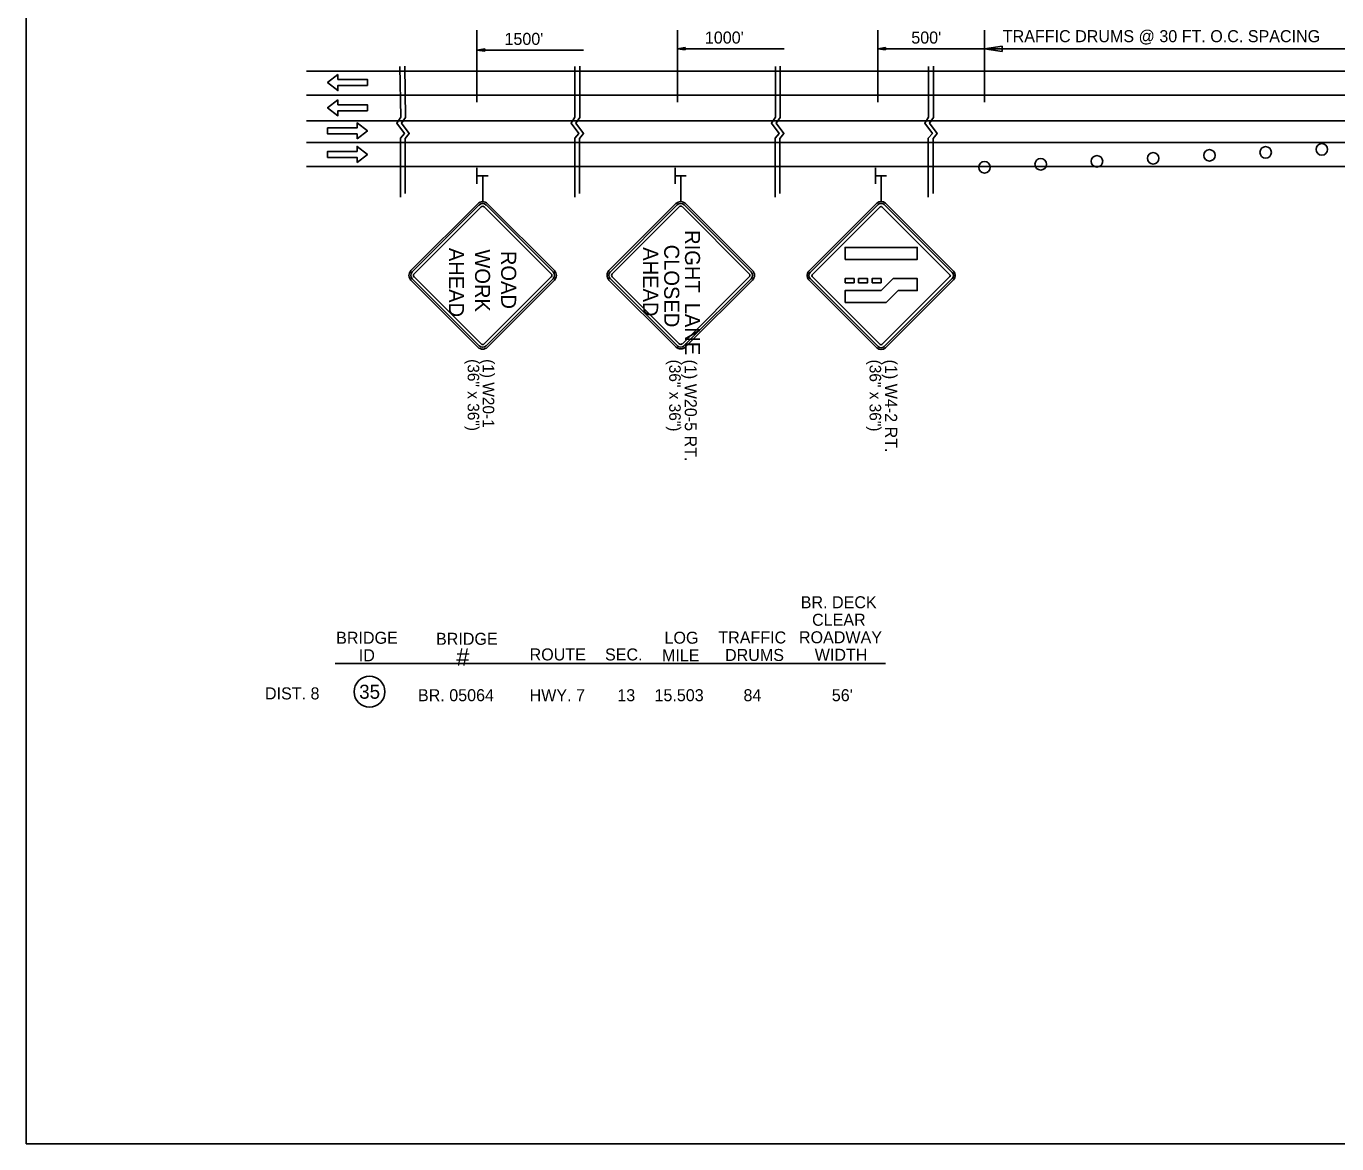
# Model space of a CAD drawing. Extents: x 1930579 to 1938013, y 596452 to 597673.
# Drawn here: x 1936313 to 1936967, y 596573 to 597131 of the extents above; entities that cross this region are included whole.
import ezdxf

# ---------------------------------------------------------------- set-up
doc = ezdxf.new("R2010")
doc.units = 0
for name, color, linetype in [('Default', 7, 'Continuous'), ('P_TC_Signs_Permanent', 7, 'Continuous'), ('P_TC_Signs_Temporary', 7, 'Continuous'), ('R_Annotation', 7, 'Continuous'), ('R_Border', 7, 'Continuous'), ('R_Striping', 7, 'Continuous')]:
    doc.layers.add(name, color=color, linetype=linetype)

msp = doc.modelspace()

# ---------------------------------------------------------------- linework, layer by layer
at = {"layer": 'Default'}
for p, q in [((1936537.79, 597129.19), (1936537.79, 597093.28)), ((1936637.79, 597129.19), (1936637.79, 597093.28)), ((1936737.79, 597129.19), (1936737.79, 597093.28)), ((1936791.02, 597129.19), (1936791.02, 597093.28)), ((1936641.62, 597120.46), (1936637.79, 597119.89)), ((1936641.62, 597119.31), (1936641.62, 597120.46)), ((1936741.62, 597120.46), (1936737.79, 597119.89)), ((1936741.62, 597119.31), (1936741.62, 597120.46)), ((1936791.02, 597119.89), (1936799.89, 597121.22)), ((1936799.89, 597121.22), (1936799.89, 597118.56)), ((1936541.62, 597119.78), (1936537.79, 597119.21)), ((1936537.79, 597119.21), (1936591.02, 597119.21)), ((1936541.62, 597118.63), (1936537.79, 597119.21)), ((1936541.62, 597119.68), (1936538.43, 597119.21)), ((1936541.62, 597118.73), (1936538.43, 597119.21)), ((1936541.62, 597119.59), (1936539.09, 597119.21)), ((1936541.62, 597118.83), (1936539.09, 597119.21)), ((1936541.62, 597119.49), (1936539.73, 597119.21)), ((1936541.62, 597118.92), (1936539.73, 597119.21)), ((1936541.62, 597119.39), (1936540.37, 597119.21)), ((1936541.62, 597119.02), (1936540.37, 597119.21)), ((1936541.62, 597119.3), (1936541.01, 597119.21)), ((1936541.62, 597119.12), (1936541.01, 597119.21)), ((1936541.62, 597118.63), (1936541.62, 597119.78)), ((1936637.79, 597119.89), (1936691.02, 597119.89)), ((1936641.62, 597119.31), (1936637.79, 597119.89)), ((1936641.62, 597120.36), (1936638.43, 597119.89)), ((1936641.62, 597119.41), (1936638.43, 597119.89)), ((1936641.62, 597120.27), (1936639.09, 597119.89)), ((1936641.62, 597119.51), (1936639.09, 597119.89)), ((1936641.62, 597120.17), (1936639.73, 597119.89)), ((1936641.62, 597119.6), (1936639.73, 597119.89)), ((1936641.62, 597120.07), (1936640.37, 597119.89)), ((1936641.62, 597119.7), (1936640.37, 597119.89)), ((1936641.62, 597119.98), (1936641.01, 597119.89)), ((1936641.62, 597119.8), (1936641.01, 597119.89)), ((1936737.79, 597119.89), (1936791.02, 597119.89)), ((1936741.62, 597119.31), (1936737.79, 597119.89)), ((1936741.62, 597120.36), (1936738.43, 597119.89)), ((1936741.62, 597119.41), (1936738.43, 597119.89)), ((1936741.62, 597120.27), (1936739.09, 597119.89)), ((1936741.62, 597119.51), (1936739.09, 597119.89)), ((1936741.62, 597120.17), (1936739.73, 597119.89)), ((1936741.62, 597119.6), (1936739.73, 597119.89)), ((1936741.62, 597120.07), (1936740.37, 597119.89)), ((1936741.62, 597119.7), (1936740.37, 597119.89)), ((1936741.62, 597119.98), (1936741.01, 597119.89)), ((1936741.62, 597119.8), (1936741.01, 597119.89)), ((1937015.53, 597119.89), (1936791.02, 597119.89)), ((1936799.89, 597118.56), (1936791.02, 597119.89)), ((1937804.86, 597108.65), (1936452.69, 597108.65)), ((1937804.86, 597096.65), (1936452.69, 597096.65)), ((1937804.86, 597083.85), (1936452.69, 597083.85)), ((1937804.86, 597073.09), (1936452.69, 597073.09)), ((1937804.86, 597061.09), (1936452.69, 597061.09)), ((1936537.79, 597052.49), (1936537.79, 597060.47)), ((1936537.91, 597056.46), (1936543.36, 597056.46)), ((1936636.62, 597052.43), (1936636.62, 597060.41)), ((1936636.74, 597056.4), (1936642.18, 597056.4)), ((1936736.62, 597052.43), (1936736.62, 597060.41)), ((1936736.74, 597056.4), (1936742.18, 597056.4))]:
    msp.add_line(p, q, dxfattribs=at)
for points in [[(1936499.33, 597110.93), (1936499.72, 597085.69), (1936497.77, 597082.8), (1936501.57, 597077.6), (1936499.57, 597075.2), (1936499.56, 597045.85)], [(1936501.73, 597111.16), (1936502.12, 597085.59), (1936500.17, 597082.7), (1936503.96, 597077.5), (1936501.96, 597075.1), (1936501.96, 597047.54)], [(1936586.69, 597110.93), (1936586.69, 597085.69), (1936584.74, 597082.8), (1936588.54, 597077.6), (1936586.54, 597075.2), (1936586.54, 597045.85)], [(1936589.09, 597111.16), (1936589.09, 597085.59), (1936587.14, 597082.7), (1936590.94, 597077.5), (1936588.94, 597075.1), (1936588.94, 597047.54)], [(1936686.69, 597110.93), (1936686.69, 597085.69), (1936684.74, 597082.8), (1936688.54, 597077.6), (1936686.54, 597075.2), (1936686.54, 597045.85)], [(1936689.09, 597111.16), (1936689.09, 597085.59), (1936687.14, 597082.7), (1936690.94, 597077.5), (1936688.94, 597075.1), (1936688.94, 597047.54)], [(1936763.16, 597110.93), (1936763.16, 597085.69), (1936761.21, 597082.8), (1936765.01, 597077.6), (1936763.01, 597075.2), (1936763, 597045.85)], [(1936765.56, 597111.16), (1936765.56, 597085.59), (1936763.61, 597082.7), (1936767.4, 597077.5), (1936765.41, 597075.1), (1936765.4, 597047.54)]]:
    msp.add_lwpolyline(points, dxfattribs=at)
for centre, radius in [((1936903.28, 597066.66), 2.87), ((1936931.34, 597068.14), 2.87), ((1936959.4, 597069.63), 2.87), ((1936791.02, 597060.71), 2.87), ((1936819.09, 597062.2), 2.87), ((1936847.15, 597063.68), 2.87), ((1936875.21, 597065.17), 2.87), ((1936484.14, 596798.97), 7.71)]:
    msp.add_circle(centre, radius, dxfattribs=at)
at = {"layer": 'P_TC_Signs_Permanent'}
for p, q in [((1936703.4, 597008.78), (1936737.34, 597042.72)), ((1936757.46, 597014.7), (1936757.46, 597020.7)), ((1936737.34, 596970.6), (1936703.4, 597004.54)), ((1936775.52, 597004.54), (1936741.58, 596970.6))]:
    msp.add_line(p, q, dxfattribs=at)
for points in [[(1936737.97, 597042.08), (1936704.03, 597008.14)], [(1936774.89, 597008.14), (1936740.94, 597042.08)], [(1936741.58, 597042.72), (1936758.55, 597025.75), (1936775.52, 597008.78)], [(1936705.09, 597007.08), (1936739.04, 597041.02)], [(1936739.88, 597041.02), (1936773.82, 597007.08)], [(1936704.03, 597005.17), (1936737.97, 596971.23)], [(1936739.04, 596972.29), (1936705.09, 597006.23)], [(1936773.82, 597006.23), (1936739.88, 596972.29)], [(1936740.94, 596971.23), (1936774.89, 597005.17)]]:
    msp.add_lwpolyline(points, dxfattribs=at)
for points in [[(1936721.46, 597014.7), (1936721.46, 597020.7), (1936757.46, 597020.7), (1936757.46, 597014.7)], [(1936721.46, 597003.06), (1936721.46, 597005.16), (1936725.96, 597005.16), (1936725.96, 597003.06)], [(1936721.46, 596993.16), (1936721.46, 596999.16), (1936739.46, 596999.16), (1936745.46, 597005.16), (1936757.46, 597005.16), (1936757.46, 596999.16), (1936747.94, 596999.16), (1936741.94, 596993.16)], [(1936728.21, 597003.06), (1936728.21, 597005.16), (1936732.71, 597005.16), (1936732.71, 597003.06)], [(1936734.96, 597003.06), (1936734.96, 597005.16), (1936739.46, 597005.16), (1936739.46, 597003.06)]]:
    msp.add_lwpolyline(points, close=True, dxfattribs=at)
for centre, radius, start, end in [((1936739.46, 597040.6), 3, 45, 135), ((1936739.46, 597040.6), 2.1, 45, 135), ((1936739.46, 597040.6), 0.6, 45, 135), ((1936705.52, 597006.66), 3, 135, 225), ((1936705.52, 597006.66), 2.1, 135, 225), ((1936705.52, 597006.66), 0.6, 135, 225), ((1936773.4, 597006.66), 0.6, 315, 45), ((1936773.4, 597006.66), 2.1, 315, 45), ((1936773.4, 597006.66), 3, 315, 45), ((1936739.46, 596972.72), 3, 225, 315), ((1936739.46, 596972.72), 2.1, 225, 315), ((1936739.46, 596972.72), 0.6, 225, 315)]:
    msp.add_arc(centre, radius, start, end, dxfattribs=at)
at = {"layer": 'P_TC_Signs_Temporary'}
for p, q in [((1936504.84, 597009.13), (1936538.25, 597042.54)), ((1936543.02, 597042.54), (1936576.43, 597009.13)), ((1936603.66, 597009.2), (1936637.07, 597042.61)), ((1936641.85, 597042.61), (1936675.26, 597009.2)), ((1936505.5, 597008.46), (1936538.91, 597041.88)), ((1936506.43, 597007.54), (1936539.84, 597040.95)), ((1936541.43, 597040.95), (1936574.84, 597007.54)), ((1936542.36, 597041.88), (1936575.77, 597008.46)), ((1936604.33, 597008.54), (1936637.74, 597041.95)), ((1936605.25, 597007.61), (1936638.66, 597041.02)), ((1936640.26, 597041.02), (1936673.67, 597007.61)), ((1936641.18, 597041.95), (1936674.59, 597008.54)), ((1936538.25, 596970.94), (1936504.84, 597004.35)), ((1936538.91, 596971.61), (1936505.5, 597005.02)), ((1936539.84, 596972.53), (1936506.43, 597005.95)), ((1936574.84, 597005.95), (1936541.43, 596972.53)), ((1936575.77, 597005.02), (1936542.36, 596971.61)), ((1936576.43, 597004.35), (1936543.02, 596970.94)), ((1936637.07, 596971.02), (1936603.66, 597004.43)), ((1936637.74, 596971.68), (1936604.33, 597005.09)), ((1936638.66, 596972.61), (1936605.25, 597006.02)), ((1936673.67, 597006.02), (1936640.26, 596972.61)), ((1936674.59, 597005.09), (1936641.18, 596971.68)), ((1936675.26, 597004.43), (1936641.85, 596971.02))]:
    msp.add_line(p, q, dxfattribs=at)
for centre, radius, start, end in [((1936540.63, 597040.15), 3.38, 45, 135), ((1936540.63, 597040.15), 2.44, 45, 135), ((1936639.46, 597040.22), 3.38, 45, 135), ((1936639.46, 597040.22), 2.44, 45, 135), ((1936540.63, 597040.15), 1.12, 45, 135), ((1936639.46, 597040.22), 1.12, 45, 135), ((1936507.22, 597006.74), 3.38, 135, 225), ((1936507.22, 597006.74), 2.44, 135, 225), ((1936507.22, 597006.74), 1.13, 135, 225), ((1936574.04, 597006.74), 1.13, 315, 45), ((1936574.04, 597006.74), 2.44, 315, 45), ((1936574.04, 597006.74), 3.38, 315, 45), ((1936606.05, 597006.81), 3.38, 135, 225), ((1936606.05, 597006.81), 2.44, 135, 225), ((1936606.05, 597006.81), 1.13, 135, 225), ((1936672.87, 597006.81), 1.13, 315, 45), ((1936672.87, 597006.81), 2.44, 315, 45), ((1936672.87, 597006.81), 3.38, 315, 45), ((1936540.63, 596973.33), 3.38, 225, 315), ((1936540.63, 596973.33), 2.44, 225, 315), ((1936540.63, 596973.33), 1.12, 225, 315), ((1936639.46, 596973.4), 3.38, 225, 315), ((1936639.46, 596973.4), 2.44, 225, 315), ((1936639.46, 596973.4), 1.12, 225, 315)]:
    msp.add_arc(centre, radius, start, end, dxfattribs=at)
at = {"layer": 'R_Annotation'}
for p, q in [((1936540.63, 597056.46), (1936540.63, 597043.53)), ((1936639.46, 597056.4), (1936639.46, 597043.6)), ((1936739.46, 597056.4), (1936739.46, 597043.6)), ((1936467.01, 596813.05), (1936741.62, 596813.05))]:
    msp.add_line(p, q, dxfattribs=at)
at = {"layer": 'R_Border'}
msp.add_lwpolyline([(1938012.84, 597673.36), (1936312.84, 597673.36), (1936312.84, 596573.37), (1938012.84, 596573.37)], close=True, dxfattribs=at)
at = {"layer": 'R_Striping'}
for points in [[(1936468.42, 597107.02), (1936463.23, 597103.02), (1936468.42, 597099.02), (1936468.42, 597101.52), (1936483.13, 597101.52), (1936483.13, 597104.52), (1936468.42, 597104.52)], [(1936468.42, 597094.38), (1936463.23, 597090.38), (1936468.42, 597086.38), (1936468.42, 597088.88), (1936483.13, 597088.88), (1936483.13, 597091.88), (1936468.42, 597091.88)], [(1936477.94, 597074.88), (1936483.13, 597078.88), (1936477.94, 597082.88), (1936477.94, 597080.38), (1936463.23, 597080.38), (1936463.23, 597077.38), (1936477.94, 597077.38)], [(1936477.94, 597063.1), (1936483.13, 597067.1), (1936477.94, 597071.1), (1936477.94, 597068.6), (1936463.23, 597068.6), (1936463.23, 597065.6), (1936477.94, 597065.6)]]:
    msp.add_lwpolyline(points, close=True, dxfattribs=at)

# ---------------------------------------------------------------- texts
at = {"layer": 'Default'}
for s, p in [("1500'", (1936551.51, 597121.78)), ("1000'", (1936651.51, 597122.45)), ("500'", (1936754.51, 597122.45)), ('TRAFFIC DRUMS @ 30 FT. O.C. SPACING', (1936800.17, 597123.14))]:
    msp.add_text(s, height=6, rotation=360, dxfattribs=at).set_placement(p)
at = {"layer": 'P_TC_Signs_Temporary'}
for s, p in [('RIGHT\u2002LANE', (1936641.59, 597029.33)), (' AHEAD ', (1936523.8, 597023.28)), ('WORK', (1936536.82, 597019.73)), (' ROAD ', (1936549.85, 597021.76)), (' AHEAD ', (1936620.71, 597023.59)), ('CLOSED', (1936631.21, 597022.07))]:
    msp.add_text(s, height=7.5, rotation=270, dxfattribs=at).set_placement(p)
at = {"layer": 'R_Annotation'}
for s, height, rotation, p in [('(36" x 36")', 5.76, 270, (1936533.14, 596964.96)), ('(1) W20-1', 5.76, 270, (1936540.63, 596964.96)), ('(36" x 36")', 5.76, 270, (1936633.7, 596964.72)), ('(1) W20-5 RT.', 6, 270, (1936641.47, 596964.72)), ('(36" x 36")', 5.76, 270, (1936733.7, 596964.72)), ('(1) W4-2 RT.', 6, 270, (1936741.47, 596964.72)), ('BR. DECK', 6, 360, (1936699.34, 596840.62)), ('CLEAR ', 6, 360, (1936704.99, 596831.88)), ('BRIDGE ', 6, 360, (1936467.51, 596822.9)), ('BRIDGE ', 6, 360, (1936517.35, 596822.38)), ('LOG', 6, 360, (1936631.36, 596822.94)), ('TRAFFIC ', 6, 360, (1936658.23, 596823.05)), ('ROADWAY ', 6, 360, (1936698.44, 596823.14)), ('ID', 6, 360, (1936478.82, 596814.17)), ('#', 8.77, 360, (1936527.49, 596811.95)), ('ROUTE', 6, 360, (1936564.04, 596814.58)), ('SEC.', 6, 360, (1936601.68, 596814.58)), ('MILE', 6, 360, (1936630.1, 596814.2)), ('DRUMS', 6, 360, (1936661.56, 596814.31)), ('WIDTH', 6, 360, (1936706.33, 596814.41)), ('DIST. 8', 6, 360, (1936432, 596795.14)), ('35', 7, 360, (1936479.01, 596795.47)), ('BR. 05064', 6, 360, (1936508.34, 596794.24)), ('HWY. 7', 6, 360, (1936564.04, 596794.24)), ('13', 6, 360, (1936607.82, 596794.24)), ('15.503', 6, 360, (1936626.37, 596794.24)), ('84', 6, 360, (1936670.77, 596794.24)), ("56'", 6, 360, (1936714.84, 596794.24))]:
    msp.add_text(s, height=height, rotation=rotation, dxfattribs=at).set_placement(p)

doc.saveas('drawing.dxf')
